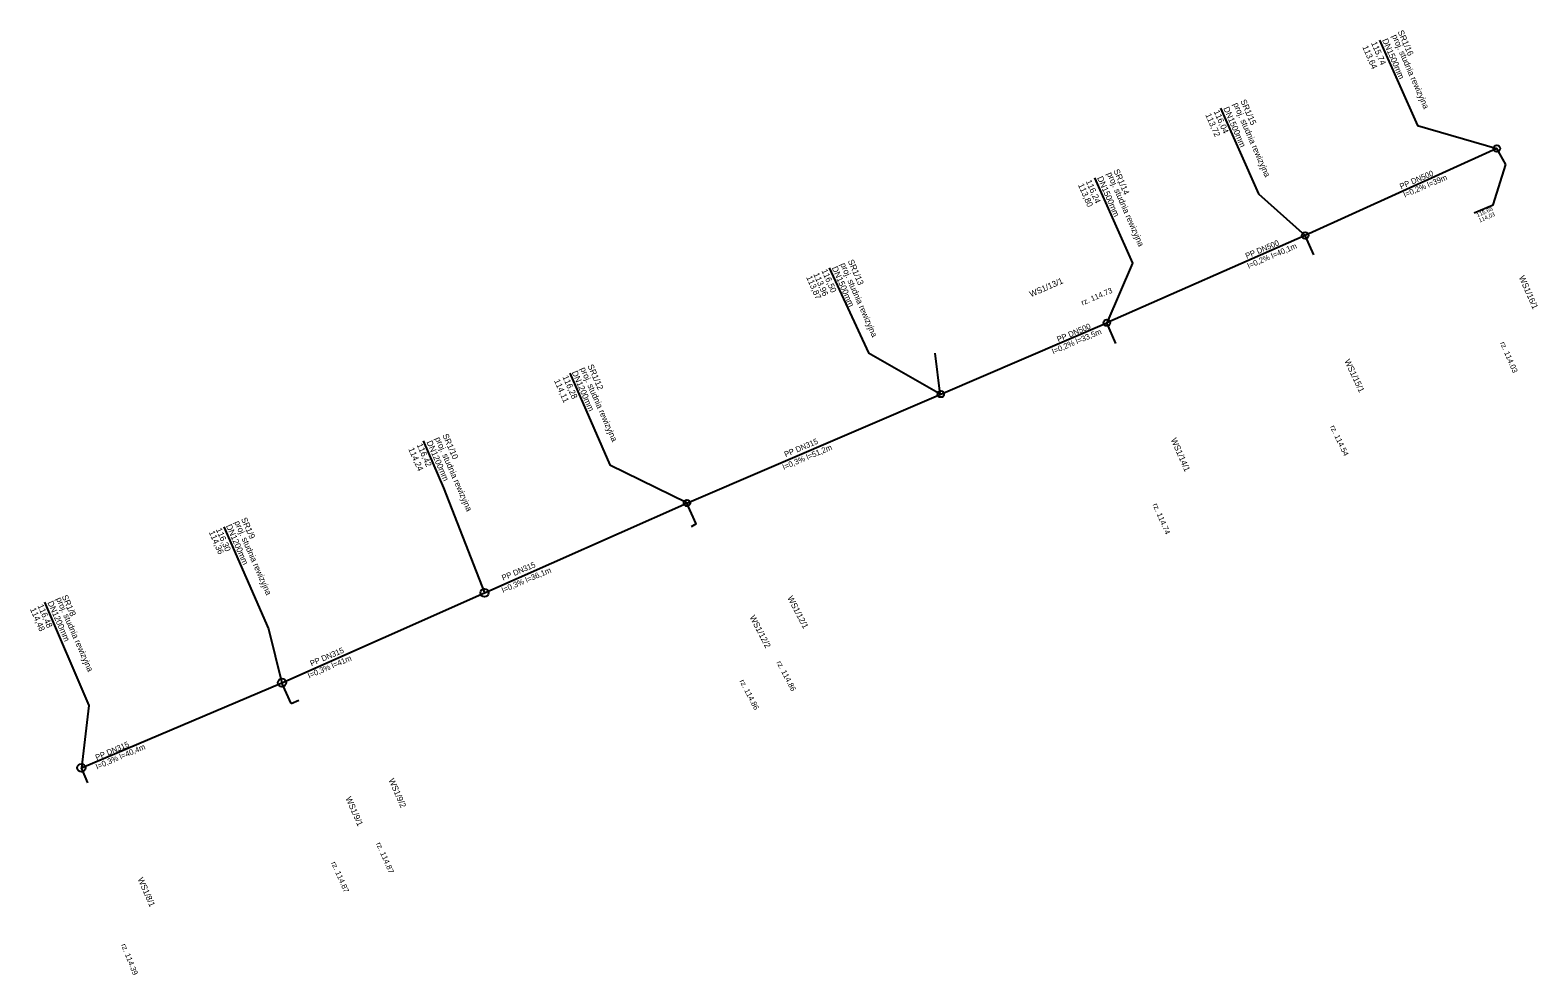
# Model space of a CAD drawing. Extents: x 7499288 to 7500494, y 5768505 to 5769051.
# Drawn here: x 7500215 to 7500494.4, y 5768876.4 to 5769051.3 of the extents above; entities that cross this region are included whole.
import ezdxf

# ---------------------------------------------------------------- set-up
doc = ezdxf.new("R2010")
doc.units = 0
for name, color, linetype in [('1_proj_kd_etap1', 7, 'Continuous'), ('2_opisy_KD_etap1', 7, 'Continuous'), ('Wpust_opis', 7, 'Continuous')]:
    doc.layers.add(name, color=color, linetype=linetype)

msp = doc.modelspace()

# ---------------------------------------------------------------- linework, layer by layer
at = {"layer": '1_proj_kd_etap1'}
for p, q in [((7500486.8, 5769029.34), (7500451.29, 5769013.23)), ((7500488.5, 5769026.35), (7500486.8, 5769029.34)), ((7500451.29, 5769013.23), (7500414.52, 5768997.05)), ((7500452.87, 5769009.62), (7500451.29, 5769013.23)), ((7500383.74, 5768983.83), (7500414.52, 5768997.05)), ((7500416.2, 5768993.18), (7500414.52, 5768997.05)), ((7500383.66, 5768983.9), (7500382.68, 5768991.44)), ((7500336.7, 5768963.64), (7500383.74, 5768983.83)), ((7500299.06, 5768946.94), (7500336.7, 5768963.64)), ((7500338.38, 5768959.77), (7500336.7, 5768963.64)), ((7500338.38, 5768959.77), (7500337.49, 5768959.25)), ((7500261.64, 5768930.34), (7500299.17, 5768946.99)), ((7500224.45, 5768914.55), (7500261.64, 5768930.34)), ((7500263.32, 5768926.47), (7500261.64, 5768930.34)), ((7500263.32, 5768926.47), (7500264.76, 5768927.09)), ((7500225.65, 5768911.8), (7500224.45, 5768914.55))]:
    msp.add_line(p, q, dxfattribs=at)
for centre, radius in [((7500486.8, 5769029.34), 0.6), ((7500451.29, 5769013.23), 0.6), ((7500414.52, 5768997.05), 0.6), ((7500383.74, 5768983.83), 0.6), ((7500336.7, 5768963.64), 0.6), ((7500299.17, 5768946.99), 0.75), ((7500261.64, 5768930.34), 0.75), ((7500224.45, 5768914.55), 0.75)]:
    msp.add_circle(centre, radius, dxfattribs=at)
at = {"layer": '2_opisy_KD_etap1'}
for points in [[(7500465.04, 5769049.42), (7500472.08, 5769033.59), (7500486.8, 5769029.34)], [(7500435.61, 5769036.79), (7500442.65, 5769020.95), (7500451.28, 5769013.22)], [(7500412.21, 5769023.91), (7500419.25, 5769008.07), (7500414.52, 5768997.05)], [(7500482.63, 5769017.39), (7500486.12, 5769018.89), (7500488.5, 5769026.35)], [(7500363.04, 5769007.21), (7500370.34, 5768991.49), (7500383.74, 5768983.83)], [(7500314.96, 5768987.72), (7500322.39, 5768970.74), (7500336.65, 5768963.72)], [(7500287.81, 5768975.15), (7500291.57, 5768966.47), (7500299.17, 5768946.99)], [(7500250.87, 5768959.2), (7500259.11, 5768940.3), (7500261.64, 5768930.34)], [(7500217.62, 5768945.28), (7500225.81, 5768926.13), (7500224.45, 5768914.55)]]:
    msp.add_lwpolyline(points, dxfattribs=at)

# ---------------------------------------------------------------- texts
for s, height, rotation, p in [('115,74', 1.125, 293.5988, (7500463.47, 5769048.89)), ('DN1500mm ', 1.125, 293.5988, (7500465.52, 5769049.43)), ('proj. studnia rewizyjna', 1.125, 293.5988, (7500467.33, 5769050.21)), ('SR1/16', 1.125, 293.5988, (7500468.4, 5769050.99)), ('113,64', 1.125, 293.5988, (7500461.85, 5769048.16)), ('proj. studnia rewizyjna', 1.125, 293.5988, (7500437.9, 5769037.57)), ('SR1/15', 1.125, 293.5988, (7500439.25, 5769038.15)), ('113,72', 1.125, 293.5988, (7500432.75, 5769035.59)), ('116,04', 1.125, 293.5988, (7500434.3, 5769036.2)), ('DN1500mm ', 1.125, 293.5988, (7500436.09, 5769036.79)), ('DN1500mm ', 1.125, 293.5988, (7500412.69, 5769023.91)), ('proj. studnia rewizyjna', 1.125, 293.5988, (7500414.5, 5769024.69)), ('SR1/14', 1.125, 293.5988, (7500415.72, 5769025.24)), ('PP DN500', 1.05, 22.9552, (7500469.07, 5769021.78)), ('I=0,2% l=39m', 1.05, 22.9552, (7500469.74, 5769020.23)), ('113,80', 1.125, 293.5988, (7500409.15, 5769022.59)), ('116,24', 1.125, 293.5988, (7500410.58, 5769023.26)), ('115,66', 0.75, 23.5988, (7500483.23, 5769016.61)), ('114,03', 0.75, 23.5988, (7500483.65, 5769015.63)), ('PP DN500', 1.05, 22.9552, (7500440.46, 5769008.89)), ('I=0,2% l=40,1m', 1.05, 22.9552, (7500440.8, 5769007.06)), ('DN1500mm ', 1.125, 293.5988, (7500363.52, 5769007.22)), ('proj. studnia rewizyjna', 1.125, 293.5988, (7500365.08, 5769007.89)), ('SR1/13', 1.125, 293.5988, (7500366.49, 5769008.49)), ('113,87', 1.125, 293.5988, (7500358.78, 5769005.48)), ('113,96', 1.125, 293.5988, (7500360.1, 5769006.05)), ('116,50', 1.125, 293.5988, (7500361.61, 5769006.72)), ('WS1/13/1', 1.125, 23.5988, (7500400.48, 5769001.77)), ('WS1/16/1', 1.125, 293.5988, (7500490.86, 5769005.49)), ('PP DN500', 1.05, 22.9552, (7500405.54, 5768993.43)), ('I=0,2% l=33,5m', 1.05, 22.9552, (7500404.59, 5768991.2)), ('WS1/15/1', 1.125, 295.1876, (7500458.52, 5768989.98)), ('DN1200mm ', 1.125, 293.5988, (7500315.32, 5768987.86)), ('proj. studnia rewizyjna', 1.125, 293.5988, (7500316.88, 5768988.53)), ('SR1/12', 1.125, 293.5988, (7500318.24, 5768989.06)), ('114,11', 1.125, 293.5988, (7500312.04, 5768986.32)), ('116,28', 1.125, 293.5988, (7500313.6, 5768987.02)), ('SR1/10', 1.125, 293.5988, (7500291.34, 5768976.21)), ('114,24', 1.125, 293.5988, (7500285.03, 5768973.65)), ('116,42', 1.125, 293.5988, (7500286.58, 5768974.42)), ('DN1200mm ', 1.125, 293.5988, (7500288.4, 5768974.93)), ('proj. studnia rewizyjna', 1.125, 293.5988, (7500289.96, 5768975.6)), ('I=0,3% l=51,2m', 1.05, 22.9552, (7500354.65, 5768969.75)), ('PP DN315', 1.05, 22.9552, (7500355, 5768972.11)), ('WS1/14/1', 1.125, 293.5988, (7500426.35, 5768975.4)), ('DN1200mm ', 1.125, 293.5988, (7500251.23, 5768959.41)), ('proj. studnia rewizyjna', 1.125, 293.5988, (7500252.79, 5768960.08)), ('SR1/9', 1.125, 293.5988, (7500254.03, 5768960.68)), ('114,36', 1.125, 293.5988, (7500248.05, 5768958.22)), ('116,30', 1.125, 293.5988, (7500249.35, 5768958.74)), ('I=0,3% l=36,1m', 1.05, 22.9552, (7500302.59, 5768946.97)), ('PP DN315', 1.05, 22.9552, (7500302.63, 5768949.23)), ('proj. studnia rewizyjna', 1.125, 293.5988, (7500219.73, 5768945.89)), ('SR1/8 ', 1.125, 293.5988, (7500220.8, 5768946.34)), ('WS1/12/1', 1.125, 297.4143, (7500355.26, 5768946.08)), ('114,48', 1.125, 293.5988, (7500214.91, 5768943.95)), ('116,48', 1.125, 293.5988, (7500216.3, 5768944.59)), ('DN1200mm ', 1.125, 293.5988, (7500218.14, 5768945.2)), ('WS1/12/2', 1.125, 297.4143, (7500348.27, 5768942.49)), ('I=0,3% l=41m', 1.05, 22.9552, (7500266.66, 5768931.12)), ('PP DN315', 1.05, 22.9552, (7500267.11, 5768933.37)), ('PP DN315', 1.05, 22.9552, (7500227.31, 5768915.95)), ('I=0,3% l=40,4m', 1.05, 22.9552, (7500227.36, 5768914.24)), ('WS1/9/2', 1.125, 293.5988, (7500281.37, 5768912.32)), ('WS1/9/1', 1.125, 293.5988, (7500273.39, 5768908.93)), ('WS1/8/1', 1.125, 293.5988, (7500234.85, 5768893.96))]:
    msp.add_text(s, height=height, rotation=rotation, dxfattribs=at).set_placement(p)
at = {"layer": 'Wpust_opis'}
for s, rotation, p in [('rz. 114.73', 23.2632, (7500410.02, 5769000.24)), ('rz. 114.03', 293.2698, (7500487.38, 5768993.29)), ('rz. 114.54', 295.418, (7500455.86, 5768977.77)), ('rz. 114.74', 293.2608, (7500422.99, 5768963.35)), ('rz. 114.86', 297.271, (7500353.27, 5768934.1)), ('rz. 114.86', 297.271, (7500346.42, 5768930.63)), ('rz. 114.87', 293.8206, (7500279.04, 5768900.5)), ('rz. 114.87', 293.8206, (7500270.72, 5768896.93)), ('rz. 114.39', 291.737, (7500231.79, 5768881.75))]:
    msp.add_text(s, height=1, rotation=rotation, dxfattribs=at).set_placement(p)

doc.saveas('drawing.dxf')
